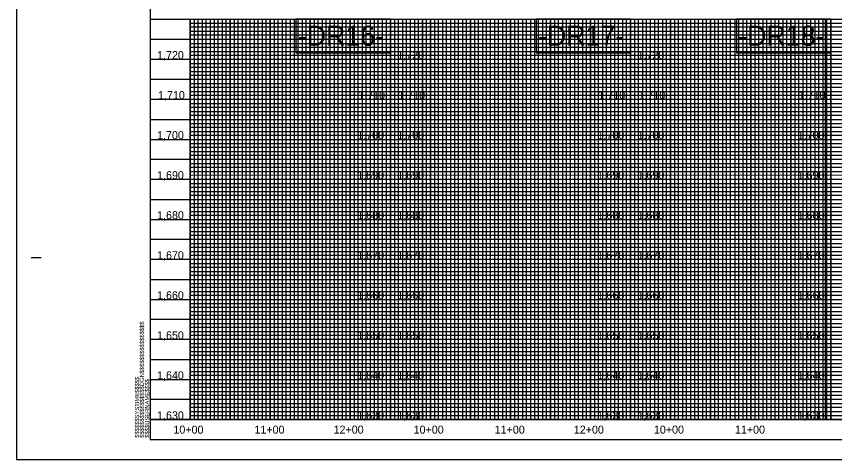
# Model space of a CAD drawing. Extents: x 505602 to 507286, y 483109 to 484209.
# Drawn here: x 505602 to 506624, y 483109 to 483662 of the extents above; entities that cross this region are included whole.
import ezdxf

# ---------------------------------------------------------------- set-up
doc = ezdxf.new("R2010")
doc.units = 0
for name, color, linetype in [('Exist Vertical Profile Vertical Axis Label', 7, 'Continuous'), ('Old_Level_1', 7, 'Continuous'), ('Prop Grid Mask', 7, 'Continuous'), ('Sheet Layout Profile Border Port 2', 7, 'Continuous'), ('Sheet Plot Border Outside CELL', 7, 'Continuous'), ('Sheet Profile CELL', 7, 'Continuous'), ('Sheet Profile Grid Major CELL', 7, 'Continuous'), ('Sheet Profile Grid Middle CELL', 7, 'Continuous'), ('Sheet Profile Grid Minor CELL', 7, 'Continuous')]:
    doc.layers.add(name, color=color, linetype=linetype)

msp = doc.modelspace()

# ---------------------------------------------------------------- linework, layer by layer
at = {"layer": 'Prop Grid Mask'}
for points in [[(506069.1, 483658.7), (505951.2, 483658.7), (505951.2, 483617), (506069.1, 483617)], [(506369.1, 483658.7), (506251.2, 483658.7), (506251.2, 483617), (506369.1, 483617)], [(506619.1, 483658.7), (506501.2, 483658.7), (506501.2, 483617), (506619.1, 483617)]]:
    msp.add_lwpolyline(points, close=True, dxfattribs=at)
at = {"layer": 'Sheet Layout Profile Border Port 2'}
for points in [[(505819.1, 483658.7), (506019.1, 483658.7), (506019.1, 483158.7), (505819.1, 483158.7)], [(506109.1, 483658.7), (506319.1, 483658.7), (506319.1, 483158.7), (506109.1, 483158.7)], [(506404.1, 483658.7), (506612, 483658.7), (506612, 483158.7), (506404.1, 483158.7)]]:
    msp.add_lwpolyline(points, close=True, dxfattribs=at)
at = {"layer": 'Sheet Plot Border Outside CELL'}
msp.add_lwpolyline([(505602.1, 483108.7), (507286.1, 483108.7), (507286.1, 484208.7), (505602.1, 484208.7)], close=True, dxfattribs=at)
at = {"layer": 'Sheet Profile CELL'}
for p, q in [((505769.1, 483658.7), (507269.1, 483658.7)), ((506069.1, 483158.7), (506069.1, 483658.7)), ((506369.1, 483158.7), (506369.1, 483658.7)), ((506619.1, 483158.7), (506619.1, 483658.7)), ((505620.6, 483361.2), (505633.1, 483361.2)), ((507269.1, 483158.7), (505769.1, 483158.7)), ((505769.1, 483133.7), (507269.1, 483133.7)), ((505769.1, 483133.7), (505769.1, 483133.7)), ((505769.1, 483133.7), (505769.1, 483133.7)), ((505769.1, 483133.7), (505769.1, 483133.7)), ((505769.1, 483133.7), (505769.1, 483133.7)), ((505769.1, 483133.7), (505769.1, 483133.7)), ((505769.1, 483133.7), (505769.1, 483133.7)), ((505769.1, 483133.7), (505769.1, 483133.7))]:
    msp.add_line(p, q, dxfattribs=at)
msp.add_lwpolyline([(507269.1, 484183.7), (505769.1, 484183.7), (505769.1, 483133.7), (507269.1, 483133.7)], close=True, dxfattribs=at)
msp.add_lwpolyline([(505806.6, 483133.7), (505806.6, 483133.7)], dxfattribs=at)
at = {"layer": 'Sheet Profile Grid Major CELL'}
for p, q in [((506269.1, 483658.7), (506319.1, 483658.7)), ((506369.1, 483658.7), (506419.1, 483658.7)), ((506469.1, 483658.7), (506519.1, 483658.7))]:
    msp.add_line(p, q, dxfattribs=at)
for points in [[(505769.1, 483658.7), (505769.1, 483158.7), (505819.1, 483158.7), (505819.1, 483658.7), (505869.1, 483658.7), (505869.1, 483158.7), (505919.1, 483158.7), (505919.1, 483658.7), (505969.1, 483658.7), (505969.1, 483158.7), (506019.1, 483158.7), (506019.1, 483658.7), (506069.1, 483658.7), (506069.1, 483158.7), (506119.1, 483158.7), (506119.1, 483658.7), (506169.1, 483658.7), (506169.1, 483158.7), (506219.1, 483158.7), (506219.1, 483658.7), (506269.1, 483658.7), (506269.1, 483158.7), (506319.1, 483158.7), (506319.1, 483658.7), (506369.1, 483658.7), (506369.1, 483158.7), (506419.1, 483158.7), (506419.1, 483658.7), (506469.1, 483658.7), (506469.1, 483158.7), (506519.1, 483158.7), (506519.1, 483658.7), (506569.1, 483658.7), (506569.1, 483158.7), (506619.1, 483158.7), (506619.1, 483658.7), (506669.1, 483658.7)], [(505819.1, 483658.7), (505819.1, 483158.7), (505869.1, 483158.7), (505869.1, 483658.7), (505919.1, 483658.7), (505919.1, 483158.7), (505969.1, 483158.7), (505969.1, 483658.7), (506019.1, 483658.7), (506019.1, 483158.7), (506069.1, 483158.7), (506069.1, 483658.7), (506119.1, 483658.7), (506119.1, 483158.7), (506169.1, 483158.7), (506169.1, 483658.7), (506219.1, 483658.7), (506219.1, 483158.7), (506269.1, 483158.7), (506269.1, 483658.7), (506319.1, 483658.7), (506319.1, 483158.7), (506369.1, 483158.7), (506369.1, 483658.7), (506419.1, 483658.7), (506419.1, 483158.7), (506469.1, 483158.7), (506469.1, 483658.7), (506519.1, 483658.7), (506519.1, 483158.7), (506569.1, 483158.7), (506569.1, 483658.7), (506619.1, 483658.7), (506619.1, 483158.7), (506669.1, 483158.7)], [(507269.1, 483608.7), (505769.1, 483608.7)], [(507269.1, 483558.7), (505769.1, 483558.7), (505769.1, 483508.7), (507269.1, 483508.7)], [(507269.1, 483458.7), (505769.1, 483458.7), (505769.1, 483408.7), (507269.1, 483408.7)], [(507269.1, 483358.7), (505769.1, 483358.7), (505769.1, 483308.7), (507269.1, 483308.7)], [(507269.1, 483258.7), (505769.1, 483258.7), (505769.1, 483258.7), (505769.1, 483208.7), (507269.1, 483208.7)], [(507269.1, 483158.7), (505769.1, 483158.7)]]:
    msp.add_lwpolyline(points, dxfattribs=at)
at = {"layer": 'Sheet Profile Grid Middle CELL'}
for points in [[(505794.1, 483658.7), (505844.1, 483658.7), (505844.1, 483158.7), (505894.1, 483158.7), (505894.1, 483658.7), (505944.1, 483658.7), (505944.1, 483158.7), (505994.1, 483158.7), (505994.1, 483658.7), (506044.1, 483658.7), (506044.1, 483158.7), (506094.1, 483158.7), (506094.1, 483658.7), (506144.1, 483658.7), (506144.1, 483158.7), (506194.1, 483158.7), (506194.1, 483658.7), (506244.1, 483658.7), (506244.1, 483158.7), (506294.1, 483158.7), (506294.1, 483658.7), (506344.1, 483658.7), (506344.1, 483158.7), (506394.1, 483158.7), (506394.1, 483158.7), (506394.1, 483658.7), (506444.1, 483658.7), (506444.1, 483158.7), (506494.1, 483158.7), (506494.1, 483658.7), (506544.1, 483658.7), (506544.1, 483158.7), (506594.1, 483158.7), (506594.1, 483658.7), (506644.1, 483658.7)], [(505769.1, 483633.7), (507269.1, 483633.7)], [(507269.1, 483583.7), (505769.1, 483583.7), (505769.1, 483533.7), (507269.1, 483533.7)], [(507269.1, 483483.7), (505769.1, 483483.7), (505769.1, 483433.7), (507269.1, 483433.7)], [(507269.1, 483383.7), (505769.1, 483383.7), (505769.1, 483333.7), (507269.1, 483333.7)], [(507269.1, 483283.7), (505769.1, 483283.7), (505769.1, 483233.7), (507269.1, 483233.7)], [(507269.1, 483183.7), (505769.1, 483183.7)]]:
    msp.add_lwpolyline(points, dxfattribs=at)
at = {"layer": 'Sheet Profile Grid Minor CELL'}
for p, q in [((505819.1, 483653.7), (507219.1, 483653.7)), ((507219.1, 483648.7), (505819.1, 483648.7)), ((505819.1, 483643.7), (507219.1, 483643.7)), ((507219.1, 483638.7), (505819.1, 483638.7)), ((505819.1, 483628.7), (507219.1, 483628.7)), ((507219.1, 483623.7), (505819.1, 483623.7)), ((505819.1, 483618.7), (507219.1, 483618.7)), ((507219.1, 483613.7), (505819.1, 483613.7)), ((505819.1, 483603.7), (507219.1, 483603.7)), ((507219.1, 483598.7), (505819.1, 483598.7)), ((505819.1, 483593.7), (507219.1, 483593.7)), ((507219.1, 483588.7), (505819.1, 483588.7)), ((505819.1, 483578.7), (507219.1, 483578.7)), ((507219.1, 483573.7), (505819.1, 483573.7)), ((505819.1, 483568.7), (507219.1, 483568.7)), ((507219.1, 483563.7), (505819.1, 483563.7)), ((505819.1, 483553.7), (507219.1, 483553.7)), ((507219.1, 483548.7), (505819.1, 483548.7)), ((505819.1, 483543.7), (507219.1, 483543.7)), ((507219.1, 483538.7), (505819.1, 483538.7)), ((505819.1, 483528.7), (507219.1, 483528.7)), ((507219.1, 483523.7), (505819.1, 483523.7)), ((505819.1, 483518.7), (507219.1, 483518.7)), ((507219.1, 483513.7), (505819.1, 483513.7)), ((505819.1, 483503.7), (507219.1, 483503.7)), ((507219.1, 483498.7), (505819.1, 483498.7)), ((505819.1, 483493.7), (507219.1, 483493.7)), ((507219.1, 483488.7), (505819.1, 483488.7)), ((505819.1, 483478.7), (507219.1, 483478.7)), ((507219.1, 483473.7), (505819.1, 483473.7)), ((505819.1, 483468.7), (507219.1, 483468.7)), ((507219.1, 483463.7), (505819.1, 483463.9)), ((505819.1, 483453.7), (507219.1, 483453.7)), ((507219.1, 483448.7), (505819.1, 483448.7)), ((505819.1, 483443.7), (507219.1, 483443.7)), ((507219.1, 483438.7), (505819.1, 483438.7)), ((505819.1, 483428.7), (507219.1, 483428.7)), ((507219.1, 483423.7), (505819.1, 483423.7)), ((505819.1, 483418.7), (507219.1, 483418.7)), ((507219.1, 483413.7), (505819.1, 483413.7)), ((505819.1, 483403.7), (507219.1, 483403.7)), ((507219.1, 483398.7), (505819.1, 483398.7)), ((505819.1, 483393.7), (507219.1, 483393.7)), ((507219.1, 483388.7), (505819.1, 483388.7)), ((505819.1, 483378.7), (507219.1, 483378.7)), ((507219.1, 483373.7), (505819.1, 483373.7)), ((505819.1, 483368.7), (507219.1, 483368.7)), ((507219.1, 483363.7), (505819.1, 483363.7)), ((505819.1, 483353.7), (507219.1, 483353.7)), ((507219.1, 483348.7), (505819.1, 483348.7)), ((505819.1, 483343.7), (507219.1, 483343.7)), ((507219.1, 483338.7), (505819.1, 483338.7)), ((505819.1, 483328.7), (507219.1, 483328.7)), ((507219.1, 483323.7), (505819.1, 483323.7)), ((505819.1, 483318.7), (507219.1, 483318.7)), ((507219.1, 483313.7), (505819.1, 483313.7)), ((505819.1, 483303.7), (507219.1, 483303.7)), ((507219.1, 483298.7), (505819.1, 483298.7)), ((505819.1, 483293.7), (507219.1, 483293.7)), ((507219.1, 483288.7), (505819.1, 483288.7)), ((505819.1, 483278.7), (507219.1, 483278.7)), ((507219.1, 483273.7), (505819.1, 483273.7)), ((505819.1, 483268.7), (507219.1, 483268.7)), ((507219.1, 483263.7), (505819.1, 483263.7)), ((505819.1, 483253.7), (507219.1, 483253.7)), ((507219.1, 483248.7), (505819.1, 483248.7)), ((505819.1, 483243.7), (507219.1, 483243.7)), ((507219.1, 483238.7), (505819.1, 483238.7)), ((505819.1, 483228.7), (507219.1, 483228.7)), ((507219.1, 483223.7), (505819.1, 483223.7)), ((505819.1, 483218.7), (507219.1, 483218.7)), ((507219.1, 483213.7), (505819.1, 483213.7)), ((505819.1, 483203.7), (507219.1, 483203.7)), ((507219.1, 483198.7), (505819.1, 483198.7)), ((505819.1, 483193.7), (507219.1, 483193.7)), ((507219.1, 483188.7), (505819.1, 483188.7)), ((505819.1, 483178.7), (507219.1, 483178.7)), ((507219.1, 483173.7), (505819.1, 483173.7)), ((505819.1, 483168.7), (507219.1, 483168.7)), ((505819.1, 483163.7), (507219.1, 483163.7))]:
    msp.add_line(p, q, dxfattribs=at)
for points in [[(505819.1, 483658.7), (505824.1, 483658.7), (505824.1, 483158.7), (505829.1, 483158.7), (505829.1, 483658.7), (505834.1, 483658.7), (505834.1, 483158.7), (505839.1, 483158.7), (505839.1, 483658.7), (505849.1, 483658.7), (505849.1, 483158.7), (505854.1, 483158.7), (505854.1, 483658.7), (505859.1, 483658.7), (505859.1, 483158.7), (505864.1, 483158.7), (505874.1, 483158.7), (505879.1, 483158.7), (505879.1, 483658.7), (505884.1, 483658.7), (505884.1, 483158.7), (505889.1, 483158.7), (505889.1, 483658.7), (505899.1, 483658.7), (505899.1, 483158.7), (505904.1, 483158.7), (505904.1, 483658.7), (505909.1, 483658.7), (505909.1, 483158.7), (505914.1, 483158.7), (505914.1, 483658.7), (505924.1, 483658.7), (505924.1, 483158.7), (505929.1, 483158.7), (505929.1, 483658.7), (505934.1, 483658.7), (505934.1, 483158.7), (505939.1, 483158.7), (505939.1, 483658.7), (505949.1, 483658.7), (505949.1, 483158.7), (505954.1, 483158.7), (505954.1, 483658.7), (505959.1, 483658.7), (505959.1, 483158.7), (505964.1, 483158.7), (505964.1, 483658.7), (505974.1, 483658.7), (505974.1, 483158.7), (505979.1, 483158.7), (505979.1, 483658.7), (505984.1, 483658.7), (505984.1, 483158.7), (505989.1, 483158.7), (505989.1, 483658.7), (505999.1, 483658.7), (505999.1, 483158.7), (506004.1, 483158.7), (506004.1, 483658.7), (506009.1, 483658.7), (506009.1, 483158.7), (506014.1, 483158.7), (506014.1, 483658.7), (506024.1, 483658.7), (506024.1, 483158.7), (506029.1, 483158.7), (506029.1, 483658.7), (506034.1, 483658.7), (506034.1, 483158.7)], [(505864.1, 483158.7), (505864.1, 483658.7), (505874.1, 483658.7), (505874.1, 483158.7)], [(506034.1, 483158.7), (506039.1, 483158.7), (506039.1, 483658.7), (506049.1, 483658.7), (506049.1, 483158.7), (506054.1, 483158.7), (506054.1, 483658.7), (506059.1, 483658.7), (506059.1, 483158.7), (506064.1, 483158.7), (506064.1, 483658.7), (506074.1, 483658.7), (506074.1, 483158.7), (506079.1, 483158.7), (506079.1, 483658.7), (506084.1, 483658.7), (506084.1, 483158.7), (506089.1, 483158.7), (506089.1, 483658.7), (506099.1, 483658.7), (506099.1, 483158.7), (506104.1, 483158.7), (506104.1, 483658.7), (506109.1, 483658.7), (506109.1, 483158.7), (506114.1, 483158.7), (506114.1, 483658.7), (506124.1, 483658.7), (506124.1, 483158.7), (506129.1, 483158.7), (506129.1, 483658.7), (506134.1, 483658.7), (506134.1, 483158.7), (506139.1, 483158.7), (506139.1, 483658.7), (506149.1, 483658.7), (506149.1, 483158.7), (506154.1, 483158.7), (506154.1, 483658.7), (506159.1, 483658.7), (506159.1, 483158.7), (506164.1, 483158.7), (506164.1, 483658.7), (506174.1, 483658.7), (506174.1, 483158.7), (506179.1, 483158.7), (506179.1, 483658.7), (506184.1, 483658.7), (506184.1, 483158.7), (506189.1, 483158.7), (506189.1, 483658.7), (506199.1, 483658.7), (506199.1, 483158.7), (506204.1, 483158.7), (506204.1, 483658.7), (506209.1, 483658.7), (506209.1, 483158.7), (506214.1, 483158.7), (506214.1, 483658.7), (506224.1, 483658.7), (506224.1, 483158.7), (506229.1, 483158.7), (506229.1, 483658.7), (506234.1, 483658.7), (506234.1, 483158.7), (506239.1, 483158.7), (506239.1, 483658.7), (506249.1, 483658.7), (506249.1, 483158.7), (506254.1, 483158.7), (506254.1, 483658.7), (506259.1, 483658.7), (506259.1, 483158.7), (506264.1, 483158.7), (506264.1, 483658.7), (506274.1, 483658.7), (506274.1, 483158.7), (506279.1, 483158.7), (506279.1, 483658.7), (506284.1, 483658.7), (506284.1, 483158.7), (506289.1, 483158.7), (506289.1, 483658.7), (506299.1, 483658.7), (506299.1, 483158.7), (506304.1, 483158.7), (506304.1, 483658.7), (506309.1, 483658.7), (506309.1, 483158.7), (506314.1, 483158.7), (506314.1, 483658.7), (506324.1, 483658.7), (506324.1, 483158.7), (506329.1, 483158.7), (506329.1, 483658.7), (506334.1, 483658.7), (506334.1, 483158.7), (506339.1, 483158.7), (506339.1, 483658.7), (506349.1, 483658.7)], [(506349.1, 483658.7), (506349.1, 483158.7), (506354.1, 483158.7), (506354.1, 483658.7), (506359.1, 483658.7), (506359.1, 483158.7), (506364.1, 483158.7), (506364.1, 483658.7), (506374.1, 483658.7), (506374.1, 483158.7), (506379.1, 483158.7), (506379.1, 483658.7), (506384.1, 483658.7), (506384.1, 483158.7), (506389.1, 483158.7), (506389.1, 483658.7), (506399.1, 483658.7), (506399.1, 483158.7), (506404.1, 483158.7), (506404.1, 483658.7), (506409.1, 483658.7), (506409.1, 483158.7), (506414.1, 483158.7), (506414.1, 483658.7), (506424.1, 483658.7), (506424.1, 483158.7), (506429.1, 483158.7), (506429.1, 483658.7), (506434.1, 483658.7), (506434.1, 483158.7), (506439.1, 483158.7), (506439.1, 483658.7), (506449.1, 483658.7), (506449.1, 483158.7), (506454.1, 483158.7), (506454.1, 483658.7), (506459.1, 483658.7), (506459.1, 483158.7), (506464.1, 483158.7), (506464.1, 483658.7), (506474.1, 483658.7), (506474.1, 483158.7), (506474.1, 483158.7), (506479.1, 483158.7), (506479.1, 483658.7), (506484.1, 483658.7), (506484.1, 483158.7), (506489.1, 483158.7), (506489.1, 483658.7), (506499.1, 483658.7), (506499.1, 483158.7), (506504.1, 483158.7), (506504.1, 483658.7), (506509.1, 483658.7), (506509.1, 483158.7), (506514.1, 483158.7), (506514.1, 483658.7), (506524.1, 483658.7), (506524.1, 483158.7), (506529.1, 483158.7), (506529.1, 483658.7), (506534.1, 483658.7), (506534.1, 483158.7), (506539.1, 483158.7), (506539.1, 483658.7), (506549.1, 483658.7), (506549.1, 483158.7), (506554.1, 483158.7), (506554.1, 483658.7), (506559.1, 483658.7), (506559.1, 483158.7), (506564.1, 483158.7), (506564.1, 483658.7), (506574.1, 483658.7), (506574.1, 483158.7), (506579.1, 483158.7), (506579.1, 483658.7), (506584.1, 483658.7), (506584.1, 483158.7), (506589.1, 483158.7), (506589.1, 483658.7), (506599.1, 483658.7), (506599.1, 483158.7), (506604.1, 483158.7), (506604.1, 483658.7), (506609.1, 483658.7), (506609.1, 483158.7), (506614.1, 483158.7), (506614.1, 483658.7), (506624.1, 483658.7)]]:
    msp.add_lwpolyline(points, dxfattribs=at)

# ---------------------------------------------------------------- texts
at = {"layer": 'Exist Vertical Profile Vertical Axis Label'}
for s, p in [('1,720', (505777.8, 483609)), ('1,720', (506077.8, 483609)), ('1,720', (506377.8, 483609)), ('1,710', (505779, 483559)), ('1,710', (506029, 483559)), ('1,710', (506079, 483559)), ('1,710', (506329, 483559)), ('1,710', (506379, 483559)), ('1,710', (506579, 483559)), ('1,700', (505777.8, 483509)), ('1,700', (506027.8, 483509)), ('1,700', (506077.8, 483509)), ('1,700', (506327.8, 483509)), ('1,700', (506377.8, 483509)), ('1,700', (506577.8, 483509)), ('1,690', (505777.8, 483459)), ('1,690', (506027.8, 483459)), ('1,690', (506077.8, 483459)), ('1,690', (506327.8, 483459)), ('1,690', (506377.8, 483459)), ('1,690', (506577.8, 483459)), ('1,680', (505777.8, 483409)), ('1,680', (506027.8, 483409)), ('1,680', (506077.8, 483409)), ('1,680', (506327.8, 483409)), ('1,680', (506377.8, 483409)), ('1,680', (506577.8, 483409)), ('1,670', (505777.8, 483359)), ('1,670', (506027.8, 483359)), ('1,670', (506077.8, 483359)), ('1,670', (506327.8, 483359)), ('1,670', (506377.8, 483359)), ('1,670', (506577.8, 483359)), ('1,660', (505777.8, 483309)), ('1,660', (506027.8, 483309)), ('1,660', (506077.8, 483309)), ('1,660', (506327.8, 483309)), ('1,660', (506377.8, 483309)), ('1,660', (506577.8, 483309)), ('1,650', (505777.8, 483259)), ('1,650', (506027.8, 483259)), ('1,650', (506077.8, 483259)), ('1,650', (506327.8, 483259)), ('1,650', (506377.8, 483259)), ('1,650', (506577.8, 483259)), ('1,640', (505777.8, 483209)), ('1,640', (506027.8, 483209)), ('1,640', (506077.8, 483209)), ('1,640', (506327.8, 483209)), ('1,640', (506377.8, 483209)), ('1,640', (506577.8, 483209)), ('1,630', (505777.8, 483159)), ('1,630', (506027.8, 483159)), ('1,630', (506077.8, 483159)), ('1,630', (506327.8, 483159)), ('1,630', (506377.8, 483159)), ('1,630', (506577.8, 483159)), ('10+00', (505798.2, 483141.2)), ('11+00', (505899.4, 483141.2)), ('12+00', (505998.2, 483141.2)), ('10+00', (506098.2, 483141.2)), ('11+00', (506199.4, 483141.2)), ('12+00', (506298.2, 483141.2)), ('10+00', (506398.2, 483141.2)), ('11+00', (506499.4, 483141.2))]:
    msp.add_text(s, height=10, dxfattribs=at).set_placement(p)
at = {"layer": 'Old_Level_1'}
for s, p in [('-DR16-', (505953.5, 483625.7)), ('-DR17-', (506253.5, 483625.7)), ('-DR18-', (506503.5, 483625.7))]:
    msp.add_text(s, height=25, dxfattribs=at).set_placement(p)
at = {"layer": 'Sheet Profile CELL'}
for s, p in [('$$$$$$$$$$$$$$$$DGN$$$$$$$$$$$$$$$$', (505761.4, 483136.1)), ('$$$$$$SYSTIME$$$$$', (505755.4, 483136.1)), ('$$$$USERNAME$$$$', (505768, 483136.1))]:
    msp.add_text(s, height=5.25, rotation=90, dxfattribs=at).set_placement(p)

doc.saveas('drawing.dxf')
